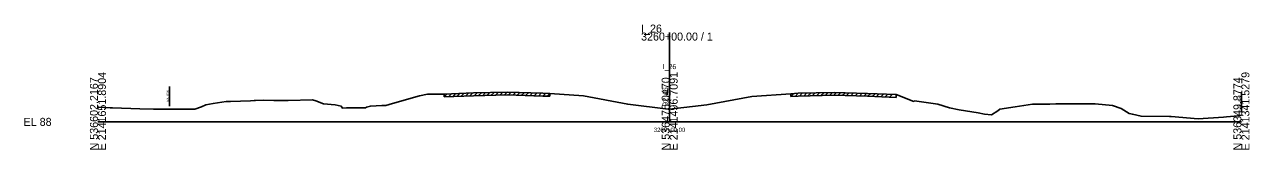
# Model space of a CAD drawing. Extents: x -13101 to 4803, y -924 to 22390.
# Drawn here: x 2974.3 to 3402.8, y 9990.3 to 10034.1 of the extents above; entities that cross this region are included whole.
import ezdxf

# ---------------------------------------------------------------- set-up
doc = ezdxf.new("R2010")
doc.units = 0
for name, color, linetype in [('RD_GPK_XS_Cell', 7, 'Continuous'), ('RD_XS_ExGround', 7, 'Continuous'), ('RD_XS_ExPaveRet', 7, 'Continuous'), ('RD_XS_ExRW', 7, 'Continuous'), ('RD_XS_TX_Baseline', 7, 'Continuous'), ('RD_XS_TX_Elev_EX', 7, 'Continuous'), ('RD_XS_TX_Station', 7, 'Continuous')]:
    doc.layers.add(name, color=color, linetype=linetype)

msp = doc.modelspace()

# ---------------------------------------------------------------- linework, layer by layer
at = {"layer": 'RD_GPK_XS_Cell'}
for p, q in [((3200, 10000), (3200, 10031.27)), ((3000, 10000), (3200, 10000)), ((3200, 10000), (3400, 10000))]:
    msp.add_line(p, q, dxfattribs=at)
at = {"layer": 'RD_XS_ExGround'}
msp.add_lwpolyline([(3000, 10005.09), (3004.27, 10004.96), (3005.08, 10004.94), (3014.69, 10004.54), (3019.46, 10004.4), (3024.69, 10004.44), (3033.94, 10004.5), (3036.24, 10005.25), (3037.72, 10005.93), (3040.34, 10006.4), (3044.88, 10007.12), (3046.34, 10007.16), (3053.41, 10007.42), (3054.7, 10007.47), (3055.1, 10007.48), (3057.88, 10007.59), (3061.54, 10007.52), (3064.5, 10007.44), (3066.49, 10007.51), (3075.11, 10007.77), (3076.23, 10007.38), (3078.93, 10006.27), (3083.01, 10005.96), (3085.1, 10005.44), (3085.5, 10004.85), (3086.98, 10004.92), (3093.56, 10004.94), (3093.89, 10005.09), (3095.29, 10005.52), (3099.33, 10005.67), (3100.7, 10005.73), (3103.09, 10006.38), (3112.47, 10009.08), (3115.3, 10009.67), (3117.31, 10009.66), (3119.21, 10009.68), (3119.77, 10009.66), (3121.1, 10009.71), (3131.35, 10010.14), (3143.11, 10010.42), (3155.63, 10010), (3158.1, 10009.95), (3169.89, 10009.09), (3185.33, 10006.17), (3199.44, 10004.4), (3200, 10004.46), (3213.04, 10006), (3228.8, 10008.83), (3242.38, 10009.84), (3244.93, 10009.99), (3257.49, 10010.3), (3269.23, 10009.97), (3279.22, 10009.57), (3285.36, 10007.18), (3285.66, 10007.35), (3293.77, 10006.16), (3297.95, 10004.93), (3301.27, 10004.26), (3307.95, 10003.15), (3310.15, 10002.68), (3312.62, 10002.49), (3314.8, 10003.9), (3315.5, 10004.4), (3320.88, 10005.28), (3325.47, 10006), (3326.9, 10006.15), (3332.97, 10006.23), (3335.1, 10006.3), (3335.38, 10006.3), (3344.07, 10006.29), (3344.82, 10006.29), (3347.08, 10006.33), (3348.81, 10006.37), (3354.97, 10005.72), (3357.99, 10004.66), (3360.73, 10002.95), (3361.87, 10002.67), (3364.9, 10001.95), (3374.83, 10001.88), (3375.4, 10001.82), (3384.9, 10001.05), (3393.72, 10001.67), (3394.84, 10001.76), (3396.2, 10001.84), (3398.69, 10002.14), (3400, 10002.34)], dxfattribs=at)
at = {"layer": 'RD_XS_ExPaveRet'}
for p, q in [((3121.1, 10008.71), (3122.14, 10009.76)), ((3121.1, 10008.71), (3121.1, 10009.71)), ((3121.1, 10008.71), (3131.35, 10009.14)), ((3122.6, 10008.77), (3123.64, 10009.82)), ((3124.1, 10008.84), (3125.14, 10009.88)), ((3125.6, 10008.9), (3126.64, 10009.94)), ((3127.1, 10008.96), (3128.14, 10010)), ((3128.6, 10009.02), (3129.64, 10010.07)), ((3130.1, 10009.09), (3131.14, 10010.13)), ((3131.35, 10009.14), (3143.11, 10009.42)), ((3131.6, 10009.14), (3132.63, 10010.17)), ((3133.1, 10009.18), (3134.13, 10010.2)), ((3134.6, 10009.22), (3135.63, 10010.24)), ((3136.1, 10009.25), (3137.13, 10010.28)), ((3137.6, 10009.29), (3138.63, 10010.31)), ((3139.1, 10009.33), (3140.13, 10010.35)), ((3140.6, 10009.36), (3141.63, 10010.39)), ((3142.1, 10009.4), (3143.12, 10010.42)), ((3143.11, 10009.42), (3155.63, 10009)), ((3143.6, 10009.41), (3144.57, 10010.37)), ((3145.1, 10009.36), (3146.07, 10010.32)), ((3146.6, 10009.31), (3147.57, 10010.27)), ((3148.1, 10009.26), (3149.07, 10010.22)), ((3149.6, 10009.2), (3150.57, 10010.17)), ((3151.1, 10009.15), (3152.07, 10010.12)), ((3152.6, 10009.1), (3153.57, 10010.07)), ((3154.1, 10009.05), (3155.07, 10010.02)), ((3155.6, 10009), (3156.58, 10009.98)), ((3155.63, 10009), (3158.1, 10008.95)), ((3157.1, 10008.97), (3158.08, 10009.95)), ((3158.1, 10009.95), (3158.1, 10008.95)), ((3242.38, 10008.84), (3243.44, 10009.9)), ((3242.38, 10008.84), (3242.38, 10009.84)), ((3242.38, 10008.84), (3244.93, 10008.99)), ((3243.88, 10008.93), (3244.94, 10009.99)), ((3244.93, 10008.99), (3257.49, 10009.3)), ((3245.38, 10009), (3246.41, 10010.02)), ((3246.88, 10009.04), (3247.91, 10010.06)), ((3248.38, 10009.07), (3249.41, 10010.1)), ((3249.88, 10009.11), (3250.91, 10010.14)), ((3251.38, 10009.15), (3252.41, 10010.17)), ((3252.88, 10009.19), (3253.91, 10010.21)), ((3254.38, 10009.22), (3255.41, 10010.25)), ((3255.88, 10009.26), (3256.91, 10010.29)), ((3257.38, 10009.3), (3258.36, 10010.28)), ((3257.49, 10009.3), (3269.23, 10008.97)), ((3258.88, 10009.26), (3259.85, 10010.24)), ((3260.38, 10009.22), (3261.35, 10010.19)), ((3261.88, 10009.18), (3262.85, 10010.15)), ((3263.38, 10009.14), (3264.35, 10010.11)), ((3264.88, 10009.09), (3265.85, 10010.07)), ((3266.38, 10009.05), (3267.35, 10010.03)), ((3267.88, 10009.01), (3268.85, 10009.98)), ((3269.23, 10008.97), (3279.22, 10008.57)), ((3269.38, 10008.97), (3270.34, 10009.93)), ((3270.88, 10008.91), (3271.84, 10009.87)), ((3272.38, 10008.85), (3273.34, 10009.81)), ((3273.88, 10008.79), (3274.84, 10009.75)), ((3275.38, 10008.73), (3276.34, 10009.69)), ((3276.88, 10008.66), (3277.84, 10009.63)), ((3279.22, 10009.57), (3279.22, 10008.57))]:
    msp.add_line(p, q, dxfattribs=at)
at = {"layer": 'RD_XS_ExRW'}
for p, q in [((3025, 10005.44), (3025, 10012.44)), ((3400, 10003.34), (3400, 10010.34))]:
    msp.add_line(p, q, dxfattribs=at)

# ---------------------------------------------------------------- texts
at = {"layer": 'RD_GPK_XS_Cell'}
for s, p in [('I_26', (3190, 10031.27)), ('3260+00.00 / 1', (3190, 10028.47)), ('EL 88', (2974, 9998.6))]:
    msp.add_text(s, height=2.8, dxfattribs=at).set_placement(p)
for s, p in [('N 536602.2167', (3000, 9990)), ('E 2141651.8904', (3002.8, 9990)), ('N 536476.0470', (3200, 9990)), ('E 2141496.7091', (3202.8, 9990)), ('N 536349.8774', (3400, 9990)), ('E 2141341.5279', (3402.8, 9990))]:
    msp.add_text(s, height=2.8, rotation=90, dxfattribs=at).set_placement(p)
at = {"layer": 'RD_XS_ExRW'}
for p in [(3024.75, 10007.12), (3399.75, 10005.02)]:
    msp.add_text('EX. R/W ', height=0.75, rotation=90, dxfattribs=at).set_placement(p)
at = {"layer": 'RD_XS_TX_Baseline'}
msp.add_text('I_26', height=1.75, dxfattribs=at).set_placement((3197.6, 10018.46))
at = {"layer": 'RD_XS_TX_Elev_EX'}
msp.add_text('92.46', height=2, rotation=90, dxfattribs=at).set_placement((3199.5, 10005.46))
at = {"layer": 'RD_XS_TX_Station'}
msp.add_text('3260+00.00', height=1.5, dxfattribs=at).set_placement((3194.45, 9996.46))

doc.saveas('drawing.dxf')
